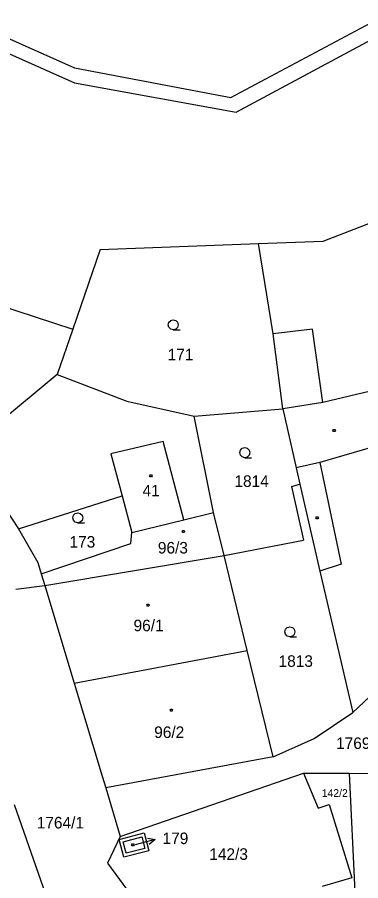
# Model space of a CAD drawing. Extents: x -799786 to -795190, y -1021716 to -1017834.
# Drawn here: x -797780.2 to -797729.6, y -1018913.6 to -1018786.5 of the extents above; entities that cross this region are included whole.
import ezdxf

# ---------------------------------------------------------------- set-up
doc = ezdxf.new("R2010")
doc.units = 0
for name, color, linetype in [('Default', 7, 'Continuous'), ('KN_HRANICE', 7, 'Continuous'), ('KN_KULTURY', 7, 'Continuous'), ('KN_PARCELY', 7, 'Continuous'), ('KN_SLUCKY', 7, 'Continuous')]:
    doc.layers.add(name, color=color, linetype=linetype)

# ---------------------------------------------------------------- blocks, each defined once
blk = doc.blocks.new('304')
at = {"layer": 'Default'}
blk.add_lwpolyline([(0, 0), (-0.38, 0.1), (-0.65, 0.37), (-0.75, 0.74), (-0.65, 1.11), (-0.38, 1.38), (-0.01, 1.48), (0.36, 1.38), (0.63, 1.11), (0.73, 0.73), (0.63, 0.35), (0.36, 0.08), (-0.02, -0.02), (0.98, -0.02)], dxfattribs=at)
blk = doc.blocks.new('NAHRADNI_SYMBOL')
at = {"layer": 'Default'}
blk.add_lwpolyline([(0.09, 0.15), (0.18, 0), (0.09, -0.15), (-0.09, -0.15), (-0.18, 0), (-0.09, 0.15), (0.09, 0.15)], dxfattribs=at)
blk = doc.blocks.new('10292')
at = {"layer": 'Default'}
blk.add_line((0, 3), (0, 0), dxfattribs=at)
blk.add_lwpolyline([(-0.5, 2), (0, 3), (0.5, 2)], dxfattribs=at)
blk = doc.blocks.new('402')
at = {"layer": 'Default'}
blk.add_lwpolyline([(0.09, 0.15), (0.18, 0), (0.09, -0.15), (-0.09, -0.15), (-0.18, 0), (-0.09, 0.15), (0.09, 0.15)], dxfattribs=at)

msp = doc.modelspace()

# ---------------------------------------------------------------- linework, layer by layer
at = {"layer": 'KN_HRANICE'}
for p, q in [((-797748.74, -1018798.28), (-797675.47, -1018759.21)), ((-797747.91, -1018800.44), (-797673.64, -1018760.45)), ((-797833.49, -1018766.66), (-797771.73, -1018793.9)), ((-797835.29, -1018767.9), (-797771.75, -1018796.11)), ((-797771.73, -1018793.9), (-797748.74, -1018798.28)), ((-797771.75, -1018796.11), (-797747.91, -1018800.44)), ((-797735.14, -1018819.43), (-797724.22, -1018815.22)), ((-797744.66, -1018819.79), (-797735.14, -1018819.43)), ((-797810.84, -1018819.71), (-797771.98, -1018832.39)), ((-797767.95, -1018820.68), (-797771.98, -1018832.39)), ((-797767.95, -1018820.68), (-797744.66, -1018819.79)), ((-797742.47, -1018833.1), (-797744.66, -1018819.79)), ((-797771.98, -1018832.39), (-797774.28, -1018839.06)), ((-797741.05, -1018844.14), (-797742.47, -1018833.1)), ((-797774.28, -1018839.06), (-797787.67, -1018850.19)), ((-797774.28, -1018839.06), (-797764.03, -1018842.98)), ((-797727.34, -1018841.32), (-797735.17, -1018843.2)), ((-797764.03, -1018842.98), (-797754.11, -1018845.18)), ((-797735.17, -1018843.2), (-797741.05, -1018844.14)), ((-797754.11, -1018845.18), (-797741.05, -1018844.14)), ((-797741.05, -1018844.14), (-797739.1, -1018852.81)), ((-797751.25, -1018859.38), (-797754.11, -1018845.18)), ((-797787.67, -1018850.19), (-797779.96, -1018861.78)), ((-797739.1, -1018852.81), (-797738.56, -1018855.23)), ((-797739.81, -1018855.54), (-797738.56, -1018855.23)), ((-797739.81, -1018855.54), (-797738, -1018863.44)), ((-797738.56, -1018855.23), (-797735.6, -1018868.01)), ((-797779.96, -1018861.78), (-797764.7, -1018856.95)), ((-797764.7, -1018856.95), (-797763.27, -1018862.31)), ((-797755.63, -1018860.47), (-797751.25, -1018859.38)), ((-797749.71, -1018865.71), (-797751.25, -1018859.38)), ((-797763.27, -1018862.31), (-797755.63, -1018860.47)), ((-797779.96, -1018861.78), (-797777.12, -1018866.75)), ((-797763.45, -1018863.93), (-797763.27, -1018862.31)), ((-797776.62, -1018868.42), (-797763.45, -1018863.93)), ((-797749.71, -1018865.71), (-797738, -1018863.44)), ((-797776.1, -1018870.15), (-797749.71, -1018865.71)), ((-797746.29, -1018879.7), (-797749.71, -1018865.71)), ((-797777.12, -1018866.75), (-797776.62, -1018868.42)), ((-797776.62, -1018868.42), (-797776.1, -1018870.15)), ((-797735.6, -1018868.01), (-797730.77, -1018888.83)), ((-797780.36, -1018870.66), (-797776.1, -1018870.15)), ((-797776.1, -1018870.15), (-797771.78, -1018884.51)), ((-797771.78, -1018884.51), (-797746.29, -1018879.7)), ((-797742.48, -1018895.34), (-797746.29, -1018879.7)), ((-797771.78, -1018884.51), (-797767.66, -1018898.19)), ((-797730.77, -1018888.83), (-797726.58, -1018884.85)), ((-797736.43, -1018892.63), (-797730.77, -1018888.83)), ((-797742.48, -1018895.34), (-797736.43, -1018892.63)), ((-797742.48, -1018895.34), (-797767.14, -1018899.93)), ((-797767.66, -1018898.19), (-797767.14, -1018899.93)), ((-797764.99, -1018907.06), (-797738.03, -1018897.74)), ((-797738.03, -1018897.74), (-797735.86, -1018902.9)), ((-797738.03, -1018897.74), (-797731.32, -1018897.77)), ((-797731.32, -1018897.77), (-797726.37, -1018897.8)), ((-797731.32, -1018897.77), (-797730.45, -1018915.2)), ((-797767.14, -1018899.93), (-797764.99, -1018907.06)), ((-797780.6, -1018902.35), (-797774.45, -1018919.96)), ((-797735.86, -1018902.9), (-797734.23, -1018902.38)), ((-797734.23, -1018902.38), (-797730.9, -1018913.14)), ((-797764.99, -1018907.06), (-797766.88, -1018911.02)), ((-797765.16, -1018907.52), (-797761.46, -1018906.51)), ((-797761.46, -1018906.51), (-797760.78, -1018909.16)), ((-797764.47, -1018910.14), (-797765.16, -1018907.52)), ((-797760.78, -1018909.16), (-797764.47, -1018910.14)), ((-797766.88, -1018911.02), (-797758.32, -1018922.62)), ((-797730.9, -1018913.14), (-797735.28, -1018914.44))]:
    msp.add_line(p, q, dxfattribs=at)
at = {"layer": 'KN_SLUCKY'}
for p, q in [((-797736.68, -1018832.41), (-797742.47, -1018833.1)), ((-797735.17, -1018843.2), (-797736.68, -1018832.41)), ((-797758.66, -1018848.92), (-797766.38, -1018850.72)), ((-797755.63, -1018860.47), (-797758.66, -1018848.92)), ((-797727.03, -1018849.53), (-797735.63, -1018852.02)), ((-797766.38, -1018850.72), (-797764.7, -1018856.95)), ((-797735.63, -1018852.02), (-797739.1, -1018852.81)), ((-797735.63, -1018852.02), (-797732.45, -1018866.97)), ((-797732.45, -1018866.97), (-797735.6, -1018868.01)), ((-797764.57, -1018907.86), (-797761.83, -1018907.12)), ((-797761.83, -1018907.12), (-797761.39, -1018908.82)), ((-797764.13, -1018909.54), (-797764.57, -1018907.86)), ((-797761.39, -1018908.82), (-797764.13, -1018909.54))]:
    msp.add_line(p, q, dxfattribs=at)

# ---------------------------------------------------------------- block references
at = {"layer": 'KN_KULTURY'}
for name, p in [('304', (-797757.18, -1018832.49)), ('402', (-797733.51, -1018847.29)), ('304', (-797746.65, -1018851.31)), ('402', (-797760.5, -1018854)), ('304', (-797771.25, -1018860.89)), ('402', (-797736, -1018860.18)), ('NAHRADNI_SYMBOL', (-797755.7, -1018862.16)), ('NAHRADNI_SYMBOL', (-797760.9, -1018873.01)), ('304', (-797740.02, -1018877.67)), ('NAHRADNI_SYMBOL', (-797757.48, -1018888.46)), ('402', (-797763.14, -1018908.29))]:
    msp.add_blockref(name, p, dxfattribs=at)
at = {"layer": 'KN_PARCELY', "rotation": -75.01079300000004}
msp.add_blockref('10292', (-797762.78, -1018908.31), dxfattribs=at)

# ---------------------------------------------------------------- texts
at = {"layer": 'KN_PARCELY'}
for s, height, p in [('171', 1.7, (-797758.02, -1018836.98)), ('1814', 1.7, (-797748.19, -1018855.61)), ('41', 1.7, (-797761.72, -1018857.01)), ('173', 1.7, (-797772.47, -1018864.55)), ('96/3', 1.7, (-797759.46, -1018865.42)), ('96/1', 1.7, (-797763.04, -1018876.86)), ('1813', 1.7, (-797741.69, -1018882.1)), ('96/2', 1.7, (-797760, -1018892.57)), ('1769/2', 1.7, (-797733.22, -1018894.19)), ('142/2', 1.14, (-797735.32, -1018901.25)), ('1764/1', 1.7, (-797777.29, -1018905.89)), ('179', 1.7, (-797758.77, -1018908.19)), ('179', 0.1, (-797762.76, -1018908.31)), ('142/3', 1.7, (-797751.89, -1018910.51))]:
    msp.add_text(s, height=height, dxfattribs=at).set_placement(p)

doc.saveas('drawing.dxf')
